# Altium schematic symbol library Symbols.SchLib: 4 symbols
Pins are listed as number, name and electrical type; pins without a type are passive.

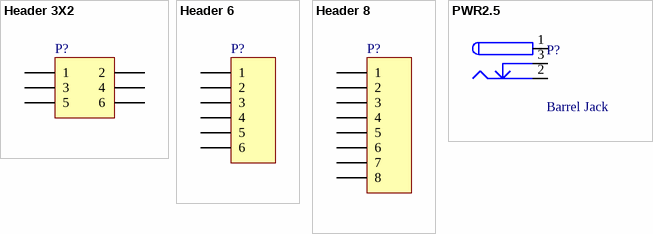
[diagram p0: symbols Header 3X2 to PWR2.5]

## Header 3X2
designator P?
Header, 3-Pin, Dual row
signal-integrity model Connector
footprint HDR2X3M (Connector; Header; 3x2 Position)
pins: 1, 2, 3, 4, 5, 6

## Header 6
designator P?
Header, 6-Pin
signal-integrity model Connector
footprint HDR1X6m (Connector; Header; 6 Position)
pins: 1, 2, 3, 4, 5, 6

## Header 8
designator P?
Header, 8-Pin
signal-integrity model Connector
footprint HDR1X8F (Connector; Header; 8 Position)
pins: 1, 2, 3, 4, 5, 6, 7, 8

## PWR2.5
designator P?, comment Barrel Jack
Low Voltage Power Supply Connector; Manufacturer: Memory Protection Devices; Manufacturer Part Number: EJ503A
footprint BARREL2.5 (DC Power Jack, 2.5mm, KLD Series, PCB Mount)
pins: 1, 2, 3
